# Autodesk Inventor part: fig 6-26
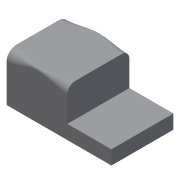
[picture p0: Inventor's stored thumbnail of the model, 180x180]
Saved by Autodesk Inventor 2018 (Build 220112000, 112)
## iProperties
Created: 2004-05
Part Number: fig 6-26
Document SubType Name: Modeling
Designer: CADCIM Technologies
Manufacturer: Standard
Standards Organization: Custom
Density: 1 g/cm^3
Material: Generic
Appearance: Default
Author: CADCIM Technologies
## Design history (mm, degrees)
node "Sketch1"
sketch "Sketch2"
  geometry: L1 (0.098, 47.711)-(0.098, 0.049); L2 (0.098, 0.049)-(-105.483, 0.049); L3 (-105.483, 0.049)-(-105.483, 14.192); L4 (-105.483, 14.192)-(-61.139, 14.192); L5 (-61.139, 14.192)-(-61.139, 47.711); L6 (-61.139, 47.711)-(0.098, 47.711)
  constraints: 12 end point, 3 parallel, 2 perpendicular, 1 vertical
extrude "Extrusion1" new body sketch "Sketch2" stored distance "d0" = 62.5; taper "d1" = 0 deg
fillet "Fillet9" dims "d61" = 10, "d62" = 8, "d63" = 2, "d64" = 5
fillet "Fillet10" dims "d65" = 8, "d66" = 10, "d67" = 2, "d68" = 5
body "Solid1"
